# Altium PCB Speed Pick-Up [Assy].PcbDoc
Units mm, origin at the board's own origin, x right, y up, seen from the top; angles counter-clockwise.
Board outline 10 x 10 mm, 2 copper layers (Top Layer, Bottom Layer), stack 1.571 mm thick; 0 components, 7 nets, 0 pads, 0 vias.
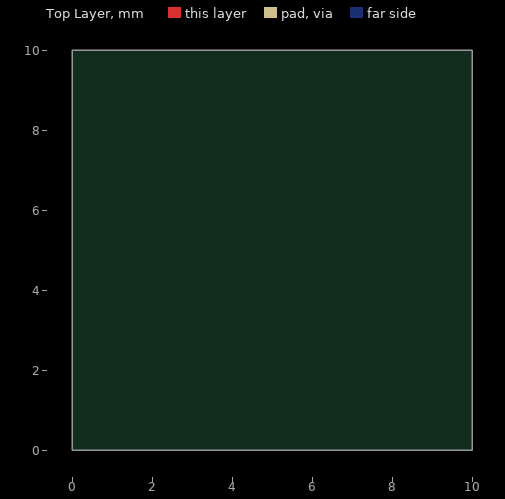
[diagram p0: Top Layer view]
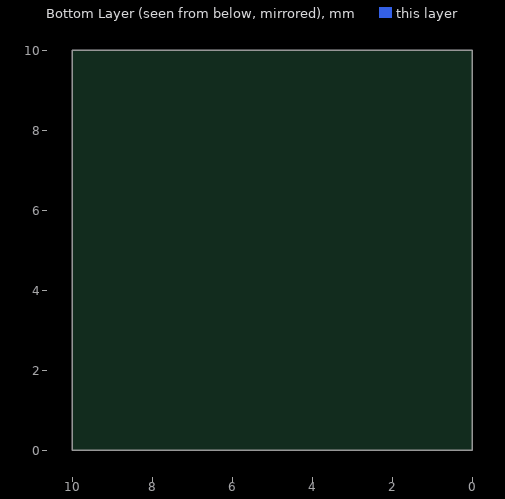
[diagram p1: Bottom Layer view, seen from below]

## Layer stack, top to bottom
Top Solder: solder mask 0.0102, Solder Resist, Dk 3.5
Top Layer: signal copper 0.0356
Dielectric1: prepreg 1.5, FR-4, Dk 4.2
Bottom Layer: signal copper 0.0356
Bottom Solder: solder mask 0.0102, Solder Resist, Dk 3.5

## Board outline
0,0 0,10 10,10 10,0

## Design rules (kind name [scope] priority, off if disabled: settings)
Clearance [All] p1: gap=0.17
ComponentClearance [All] p1: gap=0 collisioncheckmode=3 verticalgap=0.025 showdistances=FALSE
FabricationTestPointUsage TestPointUsage [All] p1: valid=0 allowmultiple=FALSE
FabricationTestpoint Testpoint [All] p1: side=3 testpointundercomponent=TRUE minsize=1.016 maxsize=2.54 preferedsize=1.524 minholesize=0 maxholesize=1.016 preferedholesize=0.813 testpointgrid=0.025 allowsidetop=TRUE allowsidebottom=TRUE usegrid=TRUE gridtolerance=0
HoleSize [All] p1: absolutevalues=TRUE maxlimit=5 minlimit=0.25 maxpercent=80.000 minpercent=20.000
PlaneClearance [All] p1: clearance=0.5
PolygonConnect PolygonConnect_8 [All vs IsNamedPolygon('Top - GND1-HSK')] p1: connectstyle=Direct reliefconductorwidth=0.254 reliefentries=4 polygonreliefangle="90 Angle" airgapwidth=0.254
PolygonConnect PolygonConnect_7 [All vs IsNamedPolygon('Bot - GND1-HSK')] p2: connectstyle=Direct reliefconductorwidth=0.254 reliefentries=4 polygonreliefangle="90 Angle" airgapwidth=0.254
PolygonConnect PolygonConnect_6 [All vs IsNamedPolygon('Bot - GND4a') Or  IsNamedPolygon('Bot - GND2a') Or  IsNamedPolygon('Bot - GND3a')] p3: connectstyle=Direct reliefconductorwidth=0.254 reliefentries=4 polygonreliefangle="90 Angle" airgapwidth=0.254
PolygonConnect PolygonConnect_5 [All vs IsNamedPolygon('Bot - GND1a')] p4: connectstyle=Direct reliefconductorwidth=0.254 reliefentries=4 polygonreliefangle="90 Angle" airgapwidth=0.254
PolygonConnect PolygonConnectVia [All vs isvia] p5: connectstyle=Direct reliefconductorwidth=0.25 reliefentries=4 polygonreliefangle="90 Angle" airgapwidth=0.254
PolygonConnect PolygonConnect_4 [All vs IsNamedPolygon('Bot - GND2')] p6: connectstyle=Relief reliefconductorwidth=0.762 reliefentries=4 polygonreliefangle="90 Angle" airgapwidth=0.254
PolygonConnect PolygonConnect_3 [All vs IsNamedPolygon('Bot - GND1')] p7: connectstyle=Relief reliefconductorwidth=0.762 reliefentries=4 polygonreliefangle="90 Angle" airgapwidth=0.254
PolygonConnect PolygonConnect_2 [All vs IsNamedPolygon('Bot - GND4')] p8: connectstyle=Relief reliefconductorwidth=0.762 reliefentries=4 polygonreliefangle="90 Angle" airgapwidth=0.254
PolygonConnect PolygonConnect_1 [All vs IsNamedPolygon('Bot - GND3')] p9: connectstyle=Relief reliefconductorwidth=0.762 reliefentries=4 polygonreliefangle="90 Angle" airgapwidth=0.254
PolygonConnect [All] p10: connectstyle=Relief reliefconductorwidth=0.4 reliefentries=4 polygonreliefangle="90 Angle" airgapwidth=0.254
RoutingCorners [All] p1: cornerstyle=45-Degree minsetback=2.5 maxsetback=2.5
RoutingVias [All] p1: holewidth=0.3 width=0.7 viastyle="Through Hole" minholewidth=0.3 minwidth=0.7 maxholewidth=0.3 maxwidth=0.7
ShortCircuit ShortCircuit_LK1 [(InComponent('LK1'))] p1: allowed=TRUE
ShortCircuit ShortCircuit_LK2 [(InComponent('LK2'))] p2: allowed=TRUE
ShortCircuit ShortCircuit_LK3 [(InComponent('LK3'))] p3: allowed=TRUE
ShortCircuit [All] p4: allowed=FALSE
SilkToSolderMaskClearance SilkscreenOverComponentPads [IsPad] p1: minsilkscreentomaskgap=0.254 clearancetoexposedcopper=TRUE
SolderMaskExpansion [All] p1: expansion=0.05
Width "Width_High Power" [InNetClass('High Power')] p1: maxlimit=1.5 minlimit=0.5 preferedwidth=1
Width Width_Power [InNetClass('Power')] p2: maxlimit=1 minlimit=0.3 preferedwidth=0.5
Width [All] p3: maxlimit=2 minlimit=0.2 preferedwidth=0.2
22 further rules are at their usual default settings.

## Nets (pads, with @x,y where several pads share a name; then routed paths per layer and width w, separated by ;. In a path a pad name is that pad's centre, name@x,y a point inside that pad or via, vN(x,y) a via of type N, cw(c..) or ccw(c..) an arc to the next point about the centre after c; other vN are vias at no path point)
FLOW_METER: 
GND: 
NetD1_2: 
NetLK1_1: 
SCL: 
SDA: 
VI: 

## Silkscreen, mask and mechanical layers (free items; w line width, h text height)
Top Assy 1:
  circle w0.125: c0,0 r2
  lines w0.2: -110.84,-47.86 -53.84,-47.86 ; -98.34,-52.86 -98.34,-47.86 ; -53.84,-42.86 42.16,-42.86 133.16,-42.86 ; -53.84,-37.86 42.16,-37.86 ; -53.84,-32.86 42.16,-32.86 ; -53.84,-27.86 42.16,-27.86 ; -37.84,-52.86 -37.84,-22.86 ; -21.84,-22.86 -21.84,-52.86 -21.84,-47.86 ; -15,10 -13,10 ; -13,0 -15,0 -15,20 -13,20 ; -5.84,-52.86 -5.84,-22.86 ; -3,0 -1,0 ; 0,-13 0,-15 20,-15 20,-13 ; 0,-3 0,-1 ; 10,-15 10,-13 ; 10.16,-52.86 10.16,-22.86 ; 26.16,-52.86 26.16,-22.86 ; 60.16,-52.86 60.16,-42.86 ; 98.16,-52.86 98.16,-42.86 ; 111.16,-52.86 111.16,-42.86 ; 133.16,-47.86 42.16,-47.86 26.16,-47.86 10.16,-47.86 -5.84,-47.86 -21.84,-47.86 ; -53.84,-52.86 -53.84,-47.86 ; -53.84,-52.86 -53.84,-47.86 ; -53.84,-52.86 -53.84,-47.86 ; -53.84,-47.86 -37.84,-47.86 -21.84,-47.86 ; -53.84,-47.86 -53.84,-22.86 ; -53.84,-22.86 42.16,-22.86 ; -53.84,-22.86 -69.84,-22.86 -110.84,-22.86 -110.84,-52.86 42.16,-52.86 ; 42.16,-52.86 133.16,-52.86 133.16,-22.86 42.16,-22.86 ; 42.16,-52.86 42.16,-22.86
  text "20" at -12,19 h2.5
  text "10" at -12,9 h2.5
  text "0" at -12,-1 h2.5
  text "0" at 1,-12 h2.5 r90
  text "10" at 11,-12 h2.5 r90
  text "20" at 21,-12 h2.5 r90
  text "TITLE" at 44.16,-25.86 h2.5
  text "AGRIGEL" at -106.615,-32.284 h10
  text ".PCB_TITLE" at 47.16,-33.86 h5
  text "TOP SIDE PLACEMENT" at 47.16,-37.86 h2.5
  text ".PCB_Drawn" at -49.84,-45.86 h2.5
  text ".PCB_Checked" at -34.84,-45.86 h2.5
  text ".PCB_Approved" at -18.84,-45.86 h2.5
  text ".PRINT_DATE" at -2.84,-45.86 h2.5
  text ".PCB_DocRevision" at 11.16,-45.86 h2.5
  text ".PCB_ECRNo" at 30.16,-45.86 h2.5
  text "DWG NUMBER" at 43.16,-45.86 h2.5
  text ".PCB_Drawing_Number" at 62.16,-45.86 h2.5
  text "PCB VER" at 99.16,-45.86 h2.5
  text "SHEET NO." at 113.16,-45.86 h2.5
  text "PLOTFILE" at -109.84,-50.86 h2.5
  text ".PCB_Plot_File_[Assy]" at -97.34,-50.86 h2.5
  text "DRAWN" at -49.84,-50.86 h2.5
  text "CHECKED" at -34.84,-50.86 h2.5
  text "APPROVED" at -19.84,-50.86 h2.5
  text "DATE" at -0.84,-50.86 h2.5
  text "DOC REV." at 13.16,-50.86 h2.5
  text "ECR NO." at 30.16,-50.86 h2.5
  text "SOURCE" at 43.16,-50.86 h2.5
  text ".Pcb_File_Name_No_Path" at 62.16,-50.86 h2.5
  text ".Version" at 101.16,-50.86 h2.5
  text "SHEET" at 113.16,-50.86 h2.5
  text "1" at 122.16,-50.86 h2.5
  text "OF" at 125.16,-50.86 h2.5
  text "1" at 130.16,-50.86 h2.5

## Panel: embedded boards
"Speed Pick-Up.PcbDoc" at 0,0, 1 rows x 1 columns, spacing 21.54 x 19.54, rotation 0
